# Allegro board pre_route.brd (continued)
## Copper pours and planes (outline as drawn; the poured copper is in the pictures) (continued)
1.5V_PLL on BOTTOM (solid shape): 239.39,45.72 239.39,40.01 238.76,39.37 227.97,39.37 227.33,40.01 227.33,45.72 227.97,46.36 238.76,46.36
1.5V_PLL on L17_PWR3 (solid shape): outline of 3802 points within 0.64,0.64 268.03,236.41
1.5V_PLL_B on TOP (solid shape): 255.91,17.91 255.91,14.61 260.73,9.78 260.73,5.46 257.43,2.16 253.11,2.16 244.47,10.79 234.31,10.79 233.04,12.06 233.04,18.41 234.31,19.69 254.13,19.69
1.5V_PLL_B on BOTTOM (solid shape): 240.03,36.83 240.03,21.59 243.2,18.41 243.2,15.24 242.57,14.61 236.85,14.61 227.33,24.13 227.33,36.83 227.97,37.46 239.39,37.46
1.5V_S_INT on BOTTOM (solid shape): 129.41,291.21 129.41,290.2 128.78,289.56 127,289.56 126.36,288.93 126.36,285.75 127,285.12 129.54,285.12 130.18,284.48 130.18,281.94 129.54,281.31 125.48,281.31 122.3,284.48 117.47,284.48 116.2,285.75 116.2,290.2 117.86,291.85 128.78,291.85
1.5V_S_INT on L5_PWR1 (solid shape): outline of 239 points within 102.55,103.31 170.5,291.78
1.5V_VCCG on L10_IS6 (solid shape): outline of 1022 points within 239.53,215.26 266.7,226.69
1.5V_VCCG on L17_PWR3 (solid shape): 246.19,216.08 246.19,213.69 246.05,213.55 239.44,213.55 238.55,212.66 229.95,212.66 229.81,212.8 229.81,214.95 229.87,214.95 229.94,214.96 230,215 230.44,215.44 230.44,216.2 230.46,216.22 246.05,216.22
1.5V_VCCP on BOTTOM (solid shape): 239.71,225.42 239.2,224.92 237.62,224.92 237.55,224.98 237.55,225.74 238.12,226.31 238.12,227.65 239.71,227.65
1.5V_VCCP on L5_PWR1 (solid shape): 239.99,226.5 240.01,226.48 240.03,226.47 240.06,226.44 240.16,226.34 240.16,225.6 239.47,224.92 238.96,224.92 238.63,224.59 238.63,221.19 238.51,221.04 238.47,220.85 238.6,220.55 238.92,220.43 239.23,220.43 239.45,220.22 239.45,219.89 239.45,219.83 239.45,213.87 239.56,213.55 239.88,213.44 240.16,213.44 240.36,213.23 245.34,213.23 245.44,213.13 245.44,211.85 244.84,211.25 244.82,211.25 229.89,211.25 229.26,211.88 229.26,213.13 229.36,213.23 236.27,213.23 236.35,213.23 238.3,213.23 238.63,213.56 238.63,218.24 238.25,218.62 238.25,218.74 238.26,218.79 238.27,218.85 238.26,218.9 238.25,218.95 238.25,219.82 238.25,219.88 238.25,220.03 238.03,220.26 237.89,220.26 237.24,220.91 237.24,222.96 237.49,223.21 237.49,226.43 237.57,226.5
1.5V_XCVR on TOP (solid shape): 268.61,17.91 268.61,14.61 273.43,9.78 273.43,5.46 270.13,2.16 265.81,2.16 262.51,5.46 262.51,11.05 259.72,13.84 259.72,18.67 260.73,19.69 266.83,19.69
1.5V_XCVR on BOTTOM (solid shape): 245.11,230.76 245.11,230.25 244.22,229.36 244.22,228.73 243.97,228.47 231.65,228.47 231.65,229.87 232.28,230.5 242.32,230.5 242.95,231.14 244.73,231.14
1.5V_XCVR on BOTTOM (solid shape): 264.29,36.07 264.29,32.26 265.68,30.86 267.21,30.86 267.97,30.1 267.97,19.69 273.43,14.22 273.43,5.46 270.13,2.16 265.81,2.16 262.51,5.46 262.51,11.3 259.72,14.1 259.72,36.2 260.35,36.83 263.53,36.83
1.5V_XCVR on L5_PWR1 (solid shape): outline of 1497 points within 195.14,28.26 279.08,249.05
1.5V_XCVR1 on BOTTOM (solid shape): 243.97,226.57 244.54,226 244.54,225.68 244.86,225.36 244.86,224.92 244.09,224.92 243.97,224.79 243.97,224.03 243.71,223.77 242.38,223.77 242.19,223.96 241.74,223.96 241.62,224.09 241.62,224.41 241.74,224.54 242.38,224.54 242.44,224.6 243.33,224.6 243.46,224.73 243.46,225.68 243.33,225.81 242.7,225.81 242.44,226.06 242.44,227.71 243.97,227.71
1.5V_XCVR1 on L5_PWR1 (solid shape): 245.05,225.92 244.95,225.72 244.91,225.5 245.15,224.98 245.71,224.83 245.88,224.83 245.9,224.81 245.9,224.37 245.87,224.35 245.79,224.35 245.74,224.35 245.69,224.35 245.14,223.8 245.69,223.25 245.74,223.25 245.79,223.25 245.9,223.25 245.94,223.21 245.94,222.22 245.8,222.05 245.75,221.84 245.77,221.73 245.81,221.62 245.55,221.37 245.55,219.24 245.45,219.14 245.45,219.13 245.44,219.11 245.44,213.57 245.36,213.49 242.53,213.49 242.44,213.58 242.44,215.57 242.27,215.75 242.27,221.07 242.05,221.28 241.7,221.28 241.68,221.3 241.66,221.31 241.43,221.54 241.43,224.5 241.64,224.5 241.66,224.51 241.73,224.5 241.81,224.49 242.2,224.65 242.36,225.04 242.35,225.16 242.32,225.27 242.32,226.34 242.48,226.5 244.47,226.5
1.5V_XCVR2 on BOTTOM (solid shape): 241.81,226.57 241.3,226.06 241.3,223.77 241.05,223.52 239.52,223.52 238.57,222.57 237.55,222.57 237.49,222.63 237.49,223.2 238.89,224.6 239.39,224.6 240.03,225.23 240.03,227.46 240.22,227.65 241.81,227.65
1.5V_XCVR2 on L5_PWR1 (solid shape): 241.3,225.27 241.27,225.16 241.25,225.04 241.26,224.94 241.29,224.84 241.17,224.72 241.17,221.44 241.45,221.16 241.45,215.64 241.65,215.44 242.02,215.44 242.19,215.28 242.19,213.58 242.1,213.49 240.46,213.49 240.26,213.69 240.26,213.81 240.26,213.87 240.26,219.83 240.15,220.14 239.85,220.27 239.82,220.27 239.78,220.26 239.29,220.75 239.3,220.8 239.31,220.85 239.18,221.15 238.89,221.27 238.89,224.48 239.07,224.66 239.57,224.66 240.41,225.5 240.41,226.32 240.59,226.5 241.3,226.5
1.5V_XCVR3 on BOTTOM (solid shape): 235.33,226.31 235.08,226.06 235.08,225.17 234.76,224.85 232.47,224.85 232.41,224.92 232.41,225.3 232.57,225.46 232.7,225.46 233.81,226.57 233.81,227.65 235.33,227.65
1.5V_XCVR3 on L5_PWR1 (solid shape): 234.7,226.39 234.7,223.45 234.19,222.94 234.19,220.42 234.44,220.17 234.44,219.07 234.44,219.01 234.44,218.85 234.57,218.55 234.88,218.44 235,218.44 235.02,218.44 235.42,218.05 235.43,218.03 235.45,218.01 235.45,217.89 235.56,217.57 235.88,217.45 236.01,217.45 236.44,217.03 236.44,216.98 236.45,216.96 236.45,216.84 236.45,215.88 236.45,215.82 236.45,215.67 236.22,215.44 236.22,213.54 236.17,213.49 234.49,213.49 234.44,213.54 234.44,215.85 234.02,216.27 232.6,216.27 232.26,216.61 232.26,216.81 232.26,216.87 232.26,218.82 232.26,218.85 232.16,219.12 231.9,219.25 231.9,226.5 234.58,226.5
1.5V_XCVR4 on BOTTOM (solid shape): 233.17,226.69 232.09,225.62 232.09,223.52 231.27,222.69 231.27,220.73 231.14,220.6 229.95,220.6 229.62,220.93 229.62,223.01 229.74,223.14 229.74,223.32 230.4,223.98 230.4,225.81 230.15,226.06 229.74,226.06 229.36,226.44 229.36,226.82 229.49,226.95 230.89,226.95 231.58,227.65 233.17,227.65
1.5V_XCVR4 on L5_PWR1 (solid shape): 230.75,226.5 231.65,226.5 231.65,219.2 231.5,219.05 231.44,218.85 231.45,218.79 231.44,218.76 231.44,216.87 231.51,216.62 231.71,216.46 231.79,216.44 231.85,216.43 231.9,216.44 231.96,216.45 232.07,216.45 232.42,216.09 232.44,216.07 232.44,215.68 232.67,215.44 232.82,215.44 232.88,215.44 233.83,215.44 233.89,215.44 234.08,215.44 234.19,215.34 234.19,213.54 234.14,213.49 229.36,213.49 229.26,213.59 229.26,220.64 229.26,220.65 229.26,226.78 229.49,227.01 230.25,227.01
1.5V_XCVR5 on BOTTOM (solid shape): 237.49,226.06 237.24,225.81 237.24,224.35 236.98,224.09 236.6,224.09 236.47,224.22 236.47,224.73 236.35,224.85 235.78,224.85 235.59,225.04 235.59,226.06 235.97,226.44 235.97,227.65 237.49,227.65
1.5V_XCVR5 on L5_PWR1 (solid shape): 237.24,226.44 237.24,223.32 236.98,223.06 236.98,220.8 237.44,220.34 237.44,220.33 237.44,219.88 237.44,219.82 237.44,218.92 237.44,218.89 237.45,218.87 237.45,218.85 237.55,218.58 237.79,218.44 237.79,218.44 237.89,218.44 238.07,218.44 238.38,218.13 238.38,213.67 238.2,213.49 236.55,213.49 236.47,213.57 236.47,215.34 236.58,215.44 236.82,215.44 236.89,215.44 237.01,215.44 237.07,215.5 237.22,215.66 237.26,215.88 237.26,216.84 237.14,217.15 236.82,217.27 236.55,217.27 236.25,217.58 236.25,217.75 236.26,217.8 236.26,217.86 236.14,218.14 235.85,218.26 235.81,218.26 235.78,218.26 235.74,218.26 235.56,218.26 235.25,218.57 235.25,218.58 235.25,218.82 235.18,219.08 234.95,219.24 234.95,220.02 234.44,220.52 234.44,222.83 234.95,223.34 234.95,226.39 235.07,226.5 237.17,226.5
1.25V on TOP (solid shape): 209.17,222.38 209.17,221.23 209.42,220.98 210.44,220.98 210.44,217.68 209.55,217.68 209.55,219.2 209.3,219.46 208.53,219.46 208.41,219.58 208.41,222.38 208.53,222.5 209.04,222.5
1.25V on TOP (solid shape): outline of 227 points within 159.38,244.35 178.44,259.08
1.25V on BOTTOM (solid shape): 178.56,240.16 178.56,235.97 178.31,235.71 175.51,235.71 174.88,236.35 174.88,239.78 175.51,240.41 178.31,240.41
1.25V on BOTTOM (solid shape): 178.56,223.77 178.56,219.58 178.31,219.33 175.51,219.33 174.88,219.96 174.88,223.39 175.51,224.03 178.31,224.03
1.25V on BOTTOM (solid shape): 178.56,213.61 178.56,209.42 178.31,209.17 175.51,209.17 174.88,209.8 174.88,213.23 175.51,213.87 178.31,213.87
1.25V on BOTTOM (solid shape): 178.56,184.28 178.56,180.09 178.31,179.83 175.51,179.83 174.88,180.47 174.88,183.9 175.51,184.53 178.31,184.53
1.25V on BOTTOM (solid shape): 178.56,167.77 178.56,163.58 178.31,163.32 175.51,163.32 174.88,163.96 174.88,167.39 175.51,168.02 178.31,168.02
1.25V on BOTTOM (solid shape): 178.69,250.44 178.69,246.25 178.44,246 175.64,246 175.01,246.63 175.01,250.06 175.64,250.7 178.44,250.7
1.25V on BOTTOM (solid shape): 178.69,156.34 178.69,152.15 178.44,151.89 175.64,151.89 175.01,152.53 175.01,155.96 175.64,156.59 178.44,156.59
1.25V on BOTTOM (solid shape): 178.69,194.56 178.69,191.13 177.55,191.13 177.55,190.37 177.29,190.12 175.64,190.12 175.01,190.75 175.01,194.18 175.64,194.82 178.44,194.82
1.25V on BOTTOM (solid shape): 178.56,142.49 178.56,138.3 178.31,138.05 176.91,138.05 176.66,138.3 176.66,138.81 176.4,139.06 174.88,139.06 174.88,142.11 175.51,142.75 178.31,142.75
1.25V on BOTTOM (solid shape): 178.94,148.21 178.94,144.02 178.69,143.76 177.93,143.76 177.55,144.14 176.66,144.14 176.28,144.53 174.75,144.53 174.75,147.57 176.28,147.57 176.66,147.95 177.29,147.95 177.8,148.46 178.69,148.46
1.25V on BOTTOM (solid shape): 178.31,176.02 178.69,176.02 178.69,172.72 177.55,172.72 177.55,171.83 177.67,171.7 177.67,168.91 177.29,168.53 176.53,168.53 175.77,169.29 174.88,169.29 174.88,176.15 175.89,176.15 176.66,176.91 177.42,176.91
1.25V on L5_PWR1 (solid shape): outline of 1859 points within 164.72,134.24 210.5,261.37
1.25V_GX_SSTL_VREF on TOP (solid shape): 148.59,272.42 148.59,270.38 147.45,269.24 147.45,264.03 147.95,263.53 151.13,263.53 151.89,262.76 151.89,258.57 151.64,258.32 147.32,258.32 146.43,259.21 146.43,272.16 147.07,272.8 148.21,272.8
1.25V_GX_SSTL_VREF on BOTTOM (solid shape): 234.44,202.39 234.44,198.42 234.26,198.25 233.43,198.25 233.25,198.42 233.25,202.39 233.43,202.56 234.26,202.56
1.25V_GX_SSTL_VREF on L4_IS2 (solid shape): outline of 7451 points within 124.46,205.1 235.61,271.4
1.25V_GX_SSTL_VREF on L15_IS9 (solid shape): outline of 392 points within 233.25,200.25 235.43,207.44
2.5V on TOP (solid shape): outline of 295 points within 152.27,251.59 175.26,285.88
2.5V on BOTTOM (solid shape): 160.02,287.66 160.02,280.67 159.38,280.04 154.31,280.04 153.67,280.67 153.67,283.21 152.4,284.48 152.4,287.91 152.78,288.29 159.38,288.29
2.5V_DDR_VDD on L17_PWR3 (solid shape): outline of 141 points within 143.32,132.91 195.77,255.46
2.5V_ENABLE on BOTTOM (solid shape): 156.21,270.26 157.35,269.11 159.45,269.11 159.45,264.16 154.56,264.16 154.05,264.67 152.27,264.67 151.76,265.18 151.76,266.06 155.45,266.06 155.45,268.1 153.42,268.1 153.42,266.06 151.76,266.06 151.76,269.88 153.03,271.15 156.21,271.15
2.5V_GX_IO on BOTTOM (solid shape): 151.76,287.66 151.76,284.1 153.03,282.83 153.03,280.54 152.53,280.04 149.22,280.04 146.69,282.58 146.69,283.97 148.48,283.97 148.48,283.94 148.48,283.88 148.5,283.82 148.52,283.76 148.56,283.7 148.59,283.65 148.64,283.6 148.69,283.57 148.74,283.53 148.8,283.51 148.86,283.49 148.92,283.48 148.99,283.48 149.05,283.48 149.11,283.5 149.17,283.52 149.23,283.55 149.28,283.58 149.33,283.63 149.37,283.68 149.4,283.73 149.43,283.79 149.45,283.85 149.46,283.91 149.47,283.97 149.46,284.04 149.45,284.1 149.43,284.16 149.4,284.22 149.37,284.27 149.33,284.32 149.28,284.36 149.23,284.4 149.17,284.43 149.11,284.45 149.05,284.46 148.99,284.47 148.92,284.47 148.86,284.46 148.8,284.44 148.74,284.41 148.69,284.38 148.64,284.34 148.59,284.29 148.56,284.24 148.52,284.19 148.5,284.13 148.48,284.07 148.48,284 148.48,283.97 146.69,283.97 146.69,287.66 147.32,288.29 151.13,288.29
2.5V_GX_IO on L17_PWR3 (solid shape): outline of 1180 points within 0.64,135.57 238.82,304.16
2.5V_OUT on TOP (solid shape): 156.21,290.83 158.11,290.83 158.11,287.02 146.05,287.02 146.05,290.83 147.95,290.83 150.5,293.37 153.67,293.37
2.5V_OUT on BOTTOM (solid shape): outline of 134 points within 148.59,264.16 174.62,293.37
2.5V_REG_IN on BOTTOM (solid shape): 159.51,274.32 161.35,274.32 161.35,264.16 160.08,264.16 160.08,269.88 157.48,269.88 156.84,270.51 156.84,271.15 156.21,271.78 154.31,271.78 153.54,272.54 153.54,275.34 154.18,275.97 157.86,275.97
3.3V on TOP (solid shape): 51.18,45.21 51.18,41.15 51.05,41.02 48.77,41.02 48.64,41.15 48.64,45.21 48.77,45.34 51.05,45.34
3.3V on TOP (solid shape): 107.31,135.64 107.31,131.06 107.06,130.81 103.76,130.81 103.5,131.06 103.5,135.64 103.76,135.89 107.06,135.89
3.3V on TOP (solid shape): 94.61,252.48 94.61,250.19 94.49,250.06 93.6,250.06 90.17,246.63 90.17,241.3 89.53,240.66 88.9,240.66 88.39,241.17 88.39,252.22 89.03,252.86 94.23,252.86
3.3V on TOP (solid shape): 271.65,202.44 271.65,201.42 271.53,201.29 270.51,201.29 270.13,200.91 270.13,199.77 270,199.64 268.35,199.64 268.22,199.77 268.22,201.42 267.97,201.68 265.94,201.68 265.94,202.69 271.4,202.69
3.3V on TOP (solid shape): 46.74,112.14 46.74,111.38 46.48,111.12 46.48,107.82 46.36,107.7 42.55,107.7 42.42,107.82 42.42,110.74 42.04,111.12 41.78,111.12 41.53,111.38 41.53,112.01 41.78,112.27 46.61,112.27
3.3V on BOTTOM (solid shape): 117.73,19.69 117.73,17.65 117.6,17.53 113.54,17.53 113.41,17.65 113.41,19.69 113.54,19.81 117.6,19.81
3.3V on BOTTOM (solid shape): 124.08,22.99 124.08,20.95 123.95,20.83 119.89,20.83 119.76,20.95 119.76,22.99 119.89,23.11 123.95,23.11
3.3V on BOTTOM (solid shape): 110.11,19.69 110.11,17.65 109.98,17.53 108.46,17.53 108.33,17.65 108.33,18.03 109.09,18.8 109.09,19.81 109.98,19.81
3.3V on L5_PWR1 (solid shape): outline of 190619 points within 0.64,0.64 329.56,304.16
3.3V_CLK1 on TOP (solid shape): 179.96,134.24 179.96,133.48 179.07,132.59 177.42,132.59 176.53,133.48 176.53,135.13 177.04,135.64 178.56,135.64
3.3V_CLK1 on TOP (solid shape): outline of 652 points within 170.18,41.27 205.74,68.58
3.3V_CLK1 on L15_IS9 (solid shape): outline of 1566 points within 170.18,41.27 205.74,68.58
3.3V_CLK2 on TOP (solid shape): outline of 436 points within 172.85,85.6 203.2,108.58
3.3V_CLK2 on L15_IS9 (solid shape): outline of 611 points within 172.72,85.09 189.23,101.35
3.3V_DIV on L5_PWR1 (solid shape): 173.23,224.43 173.23,195.3 171.98,194.06 162.41,194.06 160.78,195.69 160.78,196.14 160.84,196.14 160.85,196.14 161.53,196.6 160.85,197.06 160.84,197.05 160.78,197.05 160.78,202.96 160.84,202.96 161.4,203.45 160.84,203.94 160.78,203.94 160.78,208 157.73,211.05 157.73,215.76 157.83,215.76 157.83,215.72 159.6,215.87 157.83,216.03 157.83,215.99 157.73,215.99 157.73,222.76 157.73,223.65 157.99,223.9 158.03,223.86 158.03,223.85 158.85,223.68 158.68,224.49 158.67,224.49 158.62,224.54 159.51,225.42 172.23,225.42
3.3V_ENABLE on TOP (solid shape): 50.16,273.69 50.16,265.43 49.97,265.24 45.34,265.24 45.34,271.15 44.7,271.78 36.2,271.78 26.67,262.25 26.67,257.18 26.03,256.54 24.13,256.54 23.49,257.18 23.49,265.43 34.29,276.23 47.62,276.23
3.3V_EXT_CLK on L5_PWR1 (solid shape): 145.8,186.58 145.8,169.65 136.7,160.55 132.4,164.85 132.4,187.71 144.67,187.71
3.3V_FAN_OUT on TOP (solid shape): 120.27,277.75 125.35,277.75 125.98,277.11 125.98,273.94 126.62,273.3 129.67,273.3 131.57,271.4 133.86,271.4 134.24,271.02 134.24,269.24 133.86,268.86 131.57,268.86 131.19,268.48 124.46,268.48 123.44,267.46 123.44,263.02 121.28,260.86 118.11,260.86 109.09,251.84 109.09,248.28 108.46,247.65 102.74,247.65 102.23,248.16 102.23,255.27 103,256.03 106.55,256.03 107.95,257.43 107.95,262.25 107.31,262.89 102.74,262.89 102.23,263.4 102.23,270.76 102.74,271.27 106.55,271.27 107.95,272.67 107.95,277.5 107.31,278.13 102.74,278.13 102.23,278.64 102.23,283.21 102.87,283.85 114.17,283.85
3.3V_GX_IO on TOP (solid shape): 94.61,282.96 94.61,280.67 94.49,280.54 93.6,280.54 90.17,277.11 90.17,274.07 89.79,273.69 88.77,273.69 88.39,274.07 88.39,282.7 89.03,283.34 94.23,283.34
3.3V_GX_IO on L11_PWR2 (solid shape): outline of 89532 points within 61.15,0.64 329.56,304.16
3.3V_GX_IO on L15_IS9 (solid shape): outline of 4777 points within 238.25,199.26 250.44,215.44
3.3V_GX_XCVR_AND_CLOCKS on TOP (solid shape): 50.29,259.91 44.89,259.91 44.58,259.59 44.58,256.16 44.83,255.91 44.83,249.56 44.2,248.92 40.77,248.92 40.13,249.56 40.13,255.27 39.5,255.91 34.92,255.91 34.29,256.54 34.29,260.35 34.99,261.05 50.29,261.05
3.3V_LAN on TOP (solid shape): 44.07,122.68 44.45,122.68 44.45,120.27 40.01,120.27 39.75,120.52 39.75,122.68 39.88,122.81 43.94,122.81
3.3V_LAN on L5_PWR1 (solid shape): outline of 356 points within 0.64,115.19 51.82,143.38
3.3V_PLL on L4_IS2 (solid shape): outline of 13184 points within 112.39,129.16 156.21,161.04
3.3V_PS on TOP (solid shape): 150.11,253.62 150.11,249.17 149.86,248.92 146.69,248.92 146.3,248.54 138.43,248.54 138.05,248.92 136.78,248.92 136.4,248.54 135.25,248.54 135,248.79 135,252.98 135.13,253.11 140.21,253.11 141.1,254 141.1,255.4 141.86,256.16 147.57,256.16
3.3V_PS on BOTTOM (solid shape): 149.48,259.97 149.48,254.25 150.75,252.98 150.75,250.44 150.11,249.81 143.13,249.81 142.49,250.44 142.49,259.97 143.13,260.6 148.84,260.6
3.3V_RS232 on L5_PWR1 (solid shape): 28.57,66.32 28.57,56.54 29.84,55.27 29.84,53.06 28.45,51.67 28.45,38.23 23.73,38.23 19.3,42.65 19.3,70.38 20.43,71.5 23.39,71.5
3.3V_S_IO on TOP (solid shape): 94.61,267.72 94.61,265.43 94.49,265.3 93.6,265.3 90.17,261.87 90.17,258.83 89.79,258.44 88.77,258.44 88.39,258.83 88.39,267.46 89.03,268.1 94.23,268.1
3.3V_S_IO on L11_PWR2 (solid shape): outline of 1650 points within 0.64,0.64 168.72,304.16
3.3V_S_IOB on TOP (solid shape): 102.74,261.75 107.06,261.75 107.06,257.43 106.3,256.67 102.49,256.67 101.6,255.78 101.6,254.63 101.09,254.13 93.6,254.13 90.68,257.05 90.68,261.62 93.85,264.8 99.69,264.8
3.3V_S_IOB on BOTTOM (solid shape): 101.47,261.49 101.47,257.05 98.55,254.13 93.34,254.13 90.55,256.92 90.55,261.62 91.19,262.25 91.19,268.1 94.87,268.1
3.3V_SOURCE on TOP (solid shape): 134.75,259.59 134.75,256.54 135,256.29 136.02,256.29 136.27,256.54 136.27,258.57 136.4,258.7 139.95,258.7 140.59,258.06 140.59,254.25 139.95,253.62 133.6,253.62 126.87,254.88 123.09,249.17 123.21,247.95 123.57,246.78 123.57,245.62 122.94,244.98 110.74,244.98 109.98,245.75 109.98,251.46 118.62,260.1 134.24,260.1
3.3V_TEL on TOP (solid shape): 49.91,205.99 49.91,204.47 44.2,198.75 38.61,198.75 38.61,202.56 43.31,202.56 45.47,204.72 45.47,205.36 47.12,207.01 48.9,207.01
3.3V_TEL on BOTTOM (solid shape): 56.13,213.49 56.13,190.63 55.5,189.99 54.23,189.99 53.59,190.63 53.59,202.06 52.96,202.69 38.35,202.69 37.72,203.33 37.72,213.49 38.35,214.12 55.5,214.12
3.3V_XCVR_CLKS on TOP (solid shape): 68.2,252.73 68.2,247.01 67.56,246.38 59.05,246.38 58.55,246.89 58.55,252.86 59.05,253.36 67.56,253.36
3.3V_XCVR_CLKS on L7_IS4 (solid shape): outline of 27347 points within 186.69,46.36 319.41,301.62
3.3V_XCVR_CLKS on L11_PWR2 (solid shape): outline of 68534 points within 43.37,0.64 269.68,254.44
3.3V_XCVR_CLKS_SOURCE on TOP (solid shape): outline of 117 points within 33.66,222 121.28,254.63
3.3V_XPAK on L4_IS2 (solid shape): outline of 530 points within 237.62,111.76 258.95,118.36
3.3VIO_ENABLE on BOTTOM (solid shape): 139.95,279.02 139.95,273.3 139.32,272.67 137.92,272.67 137.41,273.18 137.41,279.02 138.05,279.65 139.32,279.65
3.3VM on TOP (solid shape): 37.46,201.42 37.46,198.75 41.91,194.31 41.91,186.82 38.1,186.82 38.1,191.64 32.13,197.61 32.13,202.56 36.32,202.56
3.3VM on BOTTOM (solid shape): 44.07,201.42 44.07,193.04 43.43,192.41 34.92,192.41 34.35,192.98 34.35,198.75 34.99,199.39 37.46,199.39 38.1,200.03 38.1,201.42 38.73,202.06 43.43,202.06
3.3VM on BOTTOM (solid shape): 266.19,50.04 266.19,43.94 266.06,43.82 264.16,43.82 263.53,44.45 254.63,44.45 253.62,43.43 252.09,43.43 251.84,43.69 251.84,47.37 252.73,48.26 262.38,48.26 264.29,50.16 266.06,50.16
3.3VM on L4_IS2 (solid shape): outline of 37306 points within 0.63,0.63 264.16,289.56
3.3VM_ATX on TOP (solid shape): 35.56,191.13 35.56,186.06 31.75,186.06 31.12,185.42 29.84,185.42 29.21,186.06 29.21,189.23 31.75,191.77 34.92,191.77
3.3VM_ATX on BOTTOM (solid shape): 33.02,251.46 33.02,245.11 31.75,243.84 26.67,243.84 25.4,245.11 25.4,245.75 24.13,247.01 20.95,247.01 19.05,248.92 19.05,251.46 19.69,252.09 32.38,252.09
3.3VM_ATX on L3_IS1 (solid shape): outline of 457 points within 21.59,184.66 38.73,252.09
3.3VM_ATX on L6_IS3 (solid shape): outline of 2861 points within 18.41,185.42 36.2,252.09
5V_CF on L15_IS9 (solid shape): outline of 448 points within 10.16,95.25 21.59,104.14
5V_TEL on TOP (solid shape): 50.16,187.32 50.16,179.07 48.9,177.8 37.46,177.8 36.83,178.44 36.83,183.51 38.1,184.78 41.91,184.78 45.09,187.96 49.53,187.96
5V_TEL on BOTTOM (solid shape): 56.13,188.72 56.13,177.93 55.5,177.29 45.34,177.29 44.7,177.93 44.7,188.72 45.34,189.36 55.5,189.36
5V_XPAK on L4_IS2 (solid shape): outline of 21388 points within 14.61,24.13 262.89,171.45
5VM on TOP (solid shape): 35.56,175.89 34.92,175.26 32.38,175.26 31.75,175.89 31.75,182.88 35.56,182.88
5VM on TOP (solid shape): 44.58,270.38 44.58,264.6 50.29,264.6 50.29,263.33 40.64,263.33 40.13,263.84 40.13,270.64 40.64,271.15 43.82,271.15
5VM on TOP (solid shape): 42.93,236.6 42.93,226.57 42.29,225.93 38.48,225.93 37.85,226.57 37.85,236.6 38.48,237.24 42.29,237.24
5VM on BOTTOM (solid shape): 149.22,203.45 147.83,202.06 147.83,201.42 147.07,200.66 145.41,200.66 145.41,204.98 146.05,205.61 147.07,205.61 147.45,205.99 149.22,205.99
5VM on BOTTOM (solid shape): 283.85,100.33 281.94,98.42 276.23,98.42 273.05,95.25 263.53,95.25 262.25,96.52 262.25,102.87 263.53,104.14 267.34,104.14 272.42,109.22 283.85,109.22
5VM on BOTTOM (solid shape): 62.48,197.61 62.48,179.32 61.59,178.44 61.59,171.45 60.96,170.81 57.79,170.81 56.77,171.83 56.77,197.61 57.4,198.25 61.85,198.25
5VM on BOTTOM (solid shape): 138.81,270 139.45,270 140.21,269.24 140.21,267.59 135.89,267.59 135.25,268.22 135.25,269.24 134.37,270.13 134.37,271.15 134.62,271.4 137.41,271.4
5VM on L7_IS4 (solid shape): outline of 43901 points within 1.27,58.42 161.29,290.83
5VM on L10_IS6 (solid shape): outline of 9479 points within 69.22,41.91 268.61,114.93
5VM_ATX on TOP (solid shape): 36.83,238.12 36.83,226.69 36.2,226.06 27.94,226.06 27.3,226.69 27.3,230.5 27.94,231.14 29.84,231.14 30.48,231.78 30.48,233.68 29.84,234.31 27.94,234.31 27.3,234.95 27.3,238.25 27.94,238.89 36.07,238.89
5VM_ATX on BOTTOM (solid shape): outline of 815 points within 20.32,209.55 31.75,238.76
12V_TEL on TOP (solid shape): 49.53,220.34 49.53,214 48.9,213.36 40.01,213.36 38.73,214.63 38.73,218.44 40.01,219.71 43.18,219.71 44.45,220.98 48.9,220.98
12V_TEL on BOTTOM (solid shape): 55.5,224.28 55.5,216.03 54.86,215.39 43.43,215.39 42.8,216.03 42.8,222.88 43.32,222.88 43.32,222.85 43.33,222.79 43.34,222.73 43.37,222.67 43.4,222.61 43.44,222.56 43.48,222.52 43.53,222.48 43.59,222.45 43.64,222.42 43.7,222.4 43.77,222.39 43.83,222.39 43.89,222.4 43.96,222.41 44.02,222.43 44.07,222.46 44.12,222.5 44.17,222.54 44.21,222.59 44.25,222.64 44.27,222.7 44.29,222.76 44.31,222.82 44.31,222.88 44.31,222.95 44.29,223.01 44.27,223.07 44.25,223.13 44.21,223.18 44.17,223.23 44.12,223.27 44.07,223.31 44.02,223.34 43.96,223.36 43.89,223.37 43.83,223.38 43.77,223.38 43.7,223.37 43.64,223.35 43.59,223.32 43.53,223.29 43.48,223.25 43.44,223.21 43.4,223.16 43.37,223.1 43.34,223.04 43.33,222.98 43.32,222.92 43.32,222.88 42.8,222.88 42.8,224.28 43.43,224.92 54.86,224.92
12VM on TOP (solid shape): 51.82,112.01 51.82,111.38 51.56,111.12 51.56,107.82 51.44,107.7 50.16,107.7 50.04,107.82 50.04,111.12 49.78,111.38 49.78,112.01 49.91,112.14 51.69,112.14
12VM on TOP (solid shape): 37.46,223.52 37.46,214.63 39.37,212.72 41.27,212.72 42.8,211.2 42.8,205.74 42.55,205.49 38.35,205.49 37.72,206.12 37.72,209.93 36.83,210.82 34.29,210.82 31.75,213.36 31.75,224.16 32.38,224.79 36.2,224.79
12VM_ATX on TOP (solid shape): 33.66,210.19 36.2,210.19 36.83,209.55 36.83,205.74 36.2,205.1 27.94,205.1 27.3,205.74 27.3,212.72 27.94,213.36 30.48,213.36
-48V_IN on TOP (solid shape): 121.28,205.74 121.28,200.28 117.6,196.6 110.11,196.6 105.41,201.29 105.41,207.01 106.04,207.64 119.38,207.64
-48V_IN on BOTTOM (solid shape): 123.19,204.72 123.19,201.04 118.74,196.6 112.01,196.6 111.76,196.34 106.43,196.34 105.79,196.98 105.79,204.47 108.97,207.64 120.27,207.64
-48V_PWR on TOP (solid shape): 110.49,213.36 110.49,209.55 109.85,208.91 106.04,208.91 103.5,206.38 103.5,203.2 102.87,202.56 95.25,202.56 94.61,203.2 94.61,214 95.25,214.63 109.22,214.63
-48V_PWR on BOTTOM (solid shape): 111.12,231.14 111.12,209.55 110.49,208.91 108.58,208.91 105.03,205.36 105.03,200.15 104.39,199.52 92.96,199.52 92.33,200.15 92.33,209.04 99.82,216.53 101.73,216.53 101.73,227.08 98.69,230.11 97.68,230.11 97.55,230.12 97.3,230.12 92.96,230.12 92.33,230.76 92.33,236.22 93.6,237.49 104.77,237.49
GND on TOP (solid shape): 88.01,261.62 88.01,258.95 87.5,258.44 86.36,258.44 85.72,259.08 85.72,261.62 86.36,262.25 87.38,262.25
GND on TOP (solid shape): 113.03,301.62 113.03,299.34 112.01,298.32 103.76,298.32 102.87,299.21 102.87,301.62 103.5,302.26 112.39,302.26
GND on TOP (solid shape): 144.4,87.88 144.4,85.6 144.27,85.47 140.21,85.47 140.08,85.6 140.08,87.88 140.21,88.01 144.27,88.01
GND on TOP (solid shape): 150.75,87.88 150.75,85.6 150.62,85.47 146.56,85.47 146.43,85.6 146.43,87.88 146.56,88.01 150.62,88.01
GND on TOP (solid shape): 162.18,87.88 162.18,85.6 162.05,85.47 157.99,85.47 157.86,85.6 157.86,87.88 157.99,88.01 162.05,88.01
GND on TOP (solid shape): 168.53,87.88 168.53,85.6 168.4,85.47 164.34,85.47 164.21,85.6 164.21,87.88 164.34,88.01 168.4,88.01
GND on TOP (solid shape): 88.01,246.38 88.01,241.55 87.5,241.05 84.84,241.05 84.2,241.68 84.2,244.86 86.36,247.01 87.38,247.01
GND on TOP (solid shape): 176.66,259.21 176.66,258.7 176.91,258.44 177.93,258.44 177.93,255.14 177.8,255.02 175.77,255.02 175.64,255.14 175.64,259.21 175.77,259.33 176.53,259.33
GND on TOP (solid shape): 39.37,262.89 38.73,262.25 34.29,262.25 33.02,260.99 33.02,257.81 32.19,256.98 27.56,256.98 27.56,258.7 27.94,259.08 27.94,262.25 36.83,271.15 39.37,271.15
GND on TOP (solid shape): 170.81,264.8 170.81,260.99 170.18,260.35 160.02,260.35 159.38,259.72 154.31,259.72 153.03,260.99 153.03,264.67 153.8,265.43 165.1,265.43 165.73,266.06 169.54,266.06
GND on TOP (solid shape): 69.6,44.58 69.6,44.2 68.96,43.56 68.96,42.42 68.83,42.29 64.52,42.29 64.39,42.42 64.39,43.56 63.75,44.2 63.75,44.58 64.01,44.83 69.34,44.83
GND on TOP (solid shape): 88.52,288.54 88.52,284.73 88.01,284.23 88.01,274.19 87.5,273.69 86.36,273.69 85.72,274.32 85.72,276.86 86.36,277.5 86.36,284.1 85.22,285.24 82.68,285.24 82.17,285.75 82.17,287.91 82.8,288.54 86.87,288.54 87.19,288.86 88.2,288.86
GND on TOP (solid shape): 75.95,44.58 75.95,44.2 75.31,43.56 74.02,43.56 73.89,43.43 73.89,42.39 73.79,42.29 71.75,42.29 71.67,42.38 71.67,43.4 71.5,43.56 70.74,43.56 70.1,44.2 70.1,44.58 70.36,44.83 75.69,44.83
GND on TOP (solid shape): 208.91,200.91 207.14,200.91 207.01,200.79 207.01,197.87 207.14,197.74 208.91,197.74 208.91,197.36 207.14,197.36 207.01,197.23 207.01,194.18 207.14,194.06 209.04,194.06 209.04,193.67 207.14,193.67 207.01,193.55 207.01,190.63 207.26,190.37 209.04,190.37 209.04,189.99 207.14,189.99 206.63,189.48 206.12,189.48 205.99,189.61 205.99,201.04 206.25,201.29 208.91,201.29
GND on TOP (solid shape): 158.62,211.84 158.62,203.58 158.5,203.45 151.82,203.45 151.69,203.58 151.69,206.57 151.69,209.29 151.84,209.29 151.84,206.57 152.96,206.57 152.96,208.09 154.32,208.09 154.32,208 155.89,208 157.61,208 157.61,209.32 155.89,209.32 154.32,209.32 154.32,209.23 152.96,209.23 152.96,209.29 151.69,209.29 151.69,210.49 153.16,211.96 158.5,211.96
GND on TOP (solid shape): 137.41,280.67 137.41,273.99 137.29,273.86 134.3,273.86 131.58,273.86 130.38,273.86 128.91,275.34 128.91,278.07 131.55,278.07 131.55,276.49 131.64,276.49 131.64,275.13 131.58,275.13 131.58,274.02 134.3,274.02 134.3,275.13 132.78,275.13 132.78,276.49 132.87,276.49 132.87,278.07 132.87,279.78 131.55,279.78 131.55,278.07 128.91,278.07 128.91,280.67 129.03,280.8 137.29,280.8
GND on TOP (solid shape): 131.32,267.46 131.32,266.7 131.58,266.44 131.58,266.4 131.62,266.4 132.08,265.94 135.38,265.94 135.89,265.43 135.89,261.62 134.87,260.6 124.21,260.6 123.82,260.99 123.82,264.67 125.41,264.67 125.41,262.13 126.56,262.13 126.56,264.19 127.41,265.05 127.48,265.02 130.3,265.02 131.29,264.03 131.58,264.03 131.58,263.86 134.3,263.86 134.3,264.97 131.54,264.97 131.46,264.94 130.8,265.6 130.8,266.34 129.22,266.34 129.22,265.02 129.1,265.02 129.1,266.34 127.52,266.34 127.52,266.07 127.35,266.07 125.95,264.67 123.82,264.67 123.82,267.21 124.59,267.97 130.81,267.97
GND on TOP (solid shape): 145.8,216.28 145.8,210.06 145.29,209.55 144.53,209.55 144.27,209.29 144.22,209.29 144.22,209.25 143.76,208.79 143.76,205.49 143.26,204.98 139.45,204.98 138.43,205.99 138.43,209.29 141.68,209.29 141.68,206.57 142.8,206.57 142.8,209.33 142.77,209.41 143.43,210.07 144.17,210.07 144.17,211.65 142.85,211.65 142.85,210.57 141.86,209.58 141.86,209.29 138.43,209.29 138.43,214.31 142.02,214.31 142.88,213.45 142.85,213.39 142.85,211.77 144.17,211.77 144.17,213.35 143.89,213.35 143.89,213.52 142.49,214.91 142.49,215.46 139.95,215.46 139.95,214.31 138.43,214.31 138.43,216.66 138.81,217.04 145.03,217.04
GND on TOP (solid shape): outline of 84 points within 27.05,101.22 51.69,105.66
GND on BOTTOM (solid shape): 52.96,201.42 52.96,196.98 52.32,196.34 45.34,196.34 44.7,196.98 44.7,201.42 45.34,202.06 52.32,202.06
GND on BOTTOM (solid shape): 88.52,288.16 88.52,285.75 87.88,285.12 85.09,285.12 84.45,285.75 84.45,288.29 84.96,288.8 87.88,288.8
GND on BOTTOM (solid shape): 71.37,197.61 71.37,190.63 70.74,189.99 63.75,189.99 63.12,190.63 63.12,197.61 63.75,198.25 70.74,198.25
GND on BOTTOM (solid shape): 174.37,214.5 173.1,214.5 172.72,214.12 171.83,214.12 171.7,214.25 171.7,217.3 171.83,217.42 174.37,217.42
GND on BOTTOM (solid shape): 54.86,237.62 54.86,229.36 54.23,228.73 43.05,228.73 42.8,228.98 42.8,237.62 43.43,238.25 54.23,238.25
GND on BOTTOM (solid shape): 87.76,275.21 87.76,272.03 87.12,271.4 85.09,271.4 84.45,272.03 84.45,274.96 85.34,275.84 87.12,275.84
GND on BOTTOM (solid shape): 87.76,259.97 87.76,256.79 87.12,256.16 85.09,256.16 84.45,256.79 84.45,259.72 85.34,260.6 87.12,260.6
GND on BOTTOM (solid shape): 173.1,249.81 174.37,249.81 174.37,246.89 173.1,246.89 172.21,246 171.96,246 171.7,246.25 171.7,250.44 171.83,250.57 172.34,250.57
GND on BOTTOM (solid shape): 173.1,239.65 174.37,239.65 174.37,236.73 173.1,236.73 172.21,235.84 171.96,235.84 171.7,236.09 171.7,240.28 171.83,240.41 172.34,240.41
GND on BOTTOM (solid shape): 173.1,223.14 174.37,223.14 174.37,220.22 173.1,220.22 172.21,219.33 171.96,219.33 171.7,219.58 171.7,223.77 171.83,223.9 172.34,223.9
GND on BOTTOM (solid shape): 173.1,212.98 174.37,212.98 174.37,210.06 173.1,210.06 172.21,209.17 171.96,209.17 171.7,209.42 171.7,213.61 171.83,213.74 172.34,213.74
GND on BOTTOM (solid shape): 173.1,193.93 174.37,193.93 174.37,191.01 173.1,191.01 172.21,190.12 171.96,190.12 171.7,190.37 171.7,194.56 171.83,194.69 172.34,194.69
GND on BOTTOM (solid shape): 173.1,183.77 174.37,183.77 174.37,180.85 173.1,180.85 172.21,179.96 171.96,179.96 171.7,180.21 171.7,184.4 171.83,184.53 172.34,184.53
GND on BOTTOM (solid shape): 173.1,167.26 174.37,167.26 174.37,164.34 173.1,164.34 172.21,163.45 171.96,163.45 171.7,163.7 171.7,167.89 171.83,168.02 172.34,168.02
GND on BOTTOM (solid shape): 87.76,244.73 87.76,239.52 87.12,238.89 85.09,238.89 84.45,239.52 84.45,244.47 85.34,245.36 87.12,245.36
GND on BOTTOM (solid shape): 173.1,176.15 174.37,176.15 174.37,169.42 174.24,169.29 173.1,169.29 172.34,168.53 171.7,168.53 171.58,168.66 171.58,176.78 171.7,176.91 172.34,176.91
GND on BOTTOM (solid shape): 170.31,267.72 170.31,240.79 170.18,240.66 167,240.66 165.48,242.19 155.45,242.19 154.69,242.95 154.69,262.51 155.32,263.14 161.67,263.14 161.92,263.4 161.92,266.7 162.31,267.08 162.69,267.08 163.07,266.7 163.07,263.4 163.32,263.14 168.4,263.14 168.91,263.65 168.91,267.72 169.16,267.97 170.05,267.97
GND on BOTTOM (solid shape): 174.37,156.34 174.37,151.89 174.62,151.64 175.01,151.64 175.13,151.51 175.13,150.75 175.01,150.62 174.62,150.62 174.37,150.37 174.37,149.35 174.62,149.1 175.01,149.1 175.13,148.97 175.13,148.21 175.01,148.08 174.75,148.08 174.37,147.7 174.37,144.14 174.5,144.02 174.88,144.02 175.13,143.76 175.13,143.26 174.88,143 174.5,143 174.24,142.75 174.24,138.81 174.37,138.68 175.01,138.68 175.13,138.56 175.13,138.05 175.01,137.92 173.1,137.92 172.97,138.05 172.97,155.7 172.85,155.83 170.43,155.83 170.31,155.96 170.31,156.46 170.43,156.59 174.12,156.59
GND on L2_GND1 (solid shape): outline of 5497 points within 0.64,0.64 329.56,304.16
GND_HSSI on TOP (solid shape): 309.76,215.78 321.8,215.78 330.26,215.78 330.26,199.53 326.8,199.52 306.78,199.53 287.96,199.53 287.96,204.21 288.96,204.21 288.96,201.53 303.45,201.53 303.45,213.78 288.96,213.78 288.96,211.1 287.96,211.1 287.96,215.78 301.8,215.78
GND_HSSI on TOP (solid shape): 309.76,195.46 321.8,195.46 330.26,195.46 330.26,179.21 326.8,179.2 306.78,179.21 287.96,179.21 287.96,183.89 288.96,183.89 288.96,181.21 303.45,181.21 303.45,193.46 288.96,193.46 288.96,190.78 287.96,190.78 287.96,195.46 301.8,195.46
GND_HSSI on TOP (solid shape): 309.76,175.14 321.8,175.14 330.26,175.14 330.26,158.89 326.8,158.88 306.78,158.89 287.96,158.89 287.96,163.57 288.96,163.57 288.96,160.89 303.45,160.89 303.45,173.14 288.96,173.14 288.96,170.46 287.96,170.46 287.96,175.14 301.8,175.14
GND_HSSI on TOP (solid shape): 309.76,154.82 321.8,154.82 330.26,154.82 330.26,138.57 326.8,138.56 306.78,138.57 287.96,138.57 287.96,143.25 288.96,143.25 288.96,140.57 303.45,140.57 303.45,152.82 288.96,152.82 288.96,150.14 287.96,150.14 287.96,154.82 301.8,154.82
GND_HSSI on TOP (solid shape): 76.58,269.24 76.58,255.27 75.69,254.38 58.8,254.38 57.79,253.36 57.79,247.52 56.58,246.32 50.23,246.32 47.24,249.3 47.24,255.14 47.62,255.52 50.55,255.52 51.31,256.29 51.31,261.37 51.05,261.62 47.75,261.62 47.37,262 47.37,262.38 47.75,262.76 51.05,262.76 51.31,263.02 51.31,269.37 51.82,269.88 75.95,269.88
GND_HSSI on TOP (solid shape): outline of 314 points within 307.09,273.81 330.07,288.8
GND_HSSI on TOP (solid shape): outline of 313 points within 307.09,256.67 330.07,271.65
GND_HSSI on TOP (solid shape): outline of 314 points within 307.09,239.52 330.07,254.51
GND_HSSI on TOP (solid shape): outline of 313 points within 307.09,222.38 330.07,237.36
GND_HSSI on TOP (solid shape): outline of 645 points within 317.47,13.46 332.11,137.16
GND_HSSI on TOP (solid shape): outline of 727 points within 269.88,10.79 308.61,101.6
GND_HSSI on TOP (solid shape): outline of 689 points within 244.6,237.36 293.88,260.73
GND_HSSI on BOTTOM (solid shape): outline of 431 points within 318.72,13.46 332.11,136.49
GND_HSSI on L2_GND1 (solid shape): 232.73,231.06 232.73,225.22 233.47,224.47 244.87,224.47 245.19,224.79 245.73,224.79 246.05,224.47 247.27,224.47 248.16,223.58 248.16,218.82 248.79,218.19 251.21,218.19 251.46,218.44 251.46,224.16 251.78,224.47 256.97,224.47 257.43,224.01 257.43,211.41 256.59,210.57 250.78,210.57 250.51,210.84 250.51,215.15 250.14,215.52 246.71,215.52 246.51,215.72 246.51,216.11 246.08,216.54 231.57,216.54 231.14,216.11 231.14,215.66 231,215.52 229.76,215.52 229.43,215.85 229.43,216.23 229.12,216.54 227.57,216.54 227.2,216.17 227.2,210.77 227,210.57 223.54,210.57 223.39,210.71 223.39,211.79 222.44,212.74 222.44,218.9 221.17,220.17 221.17,223.7 222.44,224.97 222.44,227.15 221.17,228.42 221.17,230.81 221.88,231.52 232.27,231.52
GND_HSSI on L2_GND1 (solid shape): outline of 306 points within 173.36,285.75 204.22,304.16
GND_HSSI on L2_GND1 (solid shape): outline of 636 points within 287.02,138.3 329.56,216.03
GND_HSSI on L4_IS2 (solid shape): outline of 430 points within 317.5,13.45 332.11,136.49
GND_HSSI on L4_IS2 (solid shape): outline of 1488 points within 305.43,220.6 330.28,290.32
GND_HSSI on L4_IS2 (solid shape): outline of 3394 points within 168.4,258.5 239.47,303.68
GND_HSSI on L4_IS2 (solid shape): outline of 5837 points within 228.47,210.44 246.63,227.71
GND_HSSI on L6_IS3 (solid shape): 231.2,227.14 231.2,220.41 231.84,219.77 231.84,219.01 231.9,218.95 231.9,218.76 231.84,218.69 231.84,218.57 231.33,218.06 231.33,217.42 231.2,217.3 230.45,217.3 230.33,217.42 230.33,217.85 230.19,218.19 229.84,218.34 229.5,218.2 229.36,217.86 229.36,217.42 229.23,217.3 228.98,217.3 228.85,217.42 228.85,217.68 228.79,217.74 228.79,217.93 228.85,218 228.85,218.69 228.79,218.76 228.79,218.95 228.85,219.01 228.85,219.27 228.93,219.34 229.83,219.34 229.84,219.34 230.2,219.49 230.35,219.85 230.35,219.87 230.46,220.9 230.45,220.94 230.3,221.29 229.95,221.44 229.93,221.44 229.29,221.44 229.17,221.55 229.17,226.24 229.24,226.24 229.26,226.22 230.11,226.57 229.26,226.91 229.24,226.9 229.17,226.9 229.17,227.52 229.36,227.71 230.63,227.71
GND_HSSI on L6_IS3 (solid shape): outline of 1181 points within 233.36,211.58 239.71,227.71
GND_HSSI on L6_IS3 (solid shape): outline of 1288 points within 239.77,211.58 246.76,227.71
GND_HSSI on L6_IS3 (solid shape): outline of 3359 points within 168.02,258.5 239.47,303.68
GND_HSSI on L9_IS5 (solid shape): outline of 732 points within 239.71,215.26 266.7,226.69
GND_HSSI on L10_IS6 (solid shape): outline of 1346 points within 223.44,237.36 313.06,290.98
GND_HSSI on L10_IS6 (solid shape): outline of 1640 points within 269.88,10.79 308.61,129.54
GND_HSSI on L14_GND3 (solid shape): outline of 6940 points within 0.64,0.64 329.56,304.16
GND_HSSI on L16_IS10 (solid shape): outline of 737 points within 172.72,85.09 189.48,101.6
GND_HSSI on L16_IS10 (solid shape): outline of 1309 points within 170.18,41.27 205.74,68.58
GND_HSSI on L16_IS10 (solid shape): outline of 1319 points within 229.29,214.25 250.39,216.08
GND_HSSI on L17_PWR3 (solid shape): outline of 2038 points within 172.66,0.64 329.56,304.16
GND_PLL on L8_GND2 (solid shape): outline of 7299 points within 0.64,0.64 329.56,304.16
GND_PLL on L17_PWR3 (solid shape): 221.66,205.04 223.09,205.04 223.58,205.53 223.58,206.04 223.73,206.18 225.09,206.18 225.23,206.04 225.23,203.15 224.22,202.14 224.22,201.75 223.95,201.49 223.6,201.49 223.46,201.63 223.46,202.26 223.09,202.63 220.8,202.63 219.53,203.9 212.65,203.9 211.5,202.76 209.22,202.76 206.95,200.48 206.95,195.4 204.15,192.61 204.15,179.5 206.95,176.71 206.95,150.7 205.68,149.43 205.68,137.84 206.31,137.21 206.31,133.17 204.65,131.51 196.88,131.51 196.56,131.19 195.83,131.19 195.77,131.25 195.77,132.64 196.15,133.02 196.15,135.19 197.18,135.19 199.6,137.6 201.25,137.6 202.76,139.11 202.76,149.65 203.64,150.54 203.64,176.23 200.85,179.02 200.85,184.96 201.49,185.6 201.49,194.23 203.26,196.01 203.26,202.49 207.03,206.25 207.26,206.25 207.39,206.12 207.39,204.85 207.77,204.47 209.42,204.47 210.44,205.49 210.44,206.76 210.88,207.2 219.5,207.2
GND_RTN on BOTTOM (solid shape): 91.06,236.6 91.06,230 100.33,220.73 100.33,218.95 91.06,209.68 91.06,198.37 96.39,193.04 99.69,193.04 101.73,195.07 111.63,195.07 112.08,194.63 118.68,194.63 119,194.31 120.02,194.31 123.19,191.13 123.19,188.59 118.62,184.02 104.65,184.02 102.87,182.25 91.19,182.25 83.44,189.99 83.44,236.22 84.71,237.49 90.17,237.49
VCCA on BOTTOM (solid shape): 23.49,139.7 23.49,135.89 22.23,134.62 18.92,134.62 18.03,135.51 18.03,139.45 18.54,139.95 23.24,139.95
VCCQP on TOP (solid shape): 144.65,265.43 145.8,265.43 146.05,265.18 146.05,263.65 145.8,263.4 144.4,263.4 143.38,264.41 143.38,264.8 143.13,265.05 140.84,265.05 140.72,265.18 140.72,266.19 140.84,266.32 143.76,266.32
VCCQP on BOTTOM (solid shape): 144.65,265.56 147.19,265.56 148.59,264.16 148.59,263.14 148.34,262.89 146.3,262.89 145.8,262.38 141.35,262.38 141.22,262.51 141.22,263.14 143.27,263.14 143.27,263.11 143.28,263.05 143.29,262.99 143.32,262.93 143.35,262.87 143.39,262.82 143.43,262.78 143.48,262.74 143.53,262.7 143.59,262.68 143.65,262.66 143.72,262.65 143.78,262.65 143.84,262.65 143.91,262.67 143.96,262.69 144.02,262.72 144.07,262.76 144.12,262.8 144.16,262.85 144.2,262.9 144.22,262.96 144.24,263.02 144.26,263.08 144.26,263.14 144.26,263.21 144.24,263.27 144.22,263.33 144.2,263.39 144.16,263.44 144.12,263.49 144.07,263.53 144.02,263.57 143.96,263.6 143.91,263.62 143.84,263.63 143.78,263.64 143.72,263.64 143.65,263.63 143.59,263.61 143.53,263.58 143.48,263.55 143.43,263.51 143.39,263.47 143.35,263.41 143.32,263.36 143.29,263.3 143.28,263.24 143.27,263.18 143.27,263.14 141.22,263.14 141.22,265.68 141.48,265.94 144.27,265.94
APS on BOTTOM (solid shape): 306.07,123.82 306.07,110.49 303.53,107.95 286.39,107.95 284.61,109.73 271.65,109.73 270.76,108.84 258.7,108.84 257.43,110.11 257.43,112.14 258.19,112.9 277.5,112.9 277.88,112.52 291.97,112.52 292.99,111.51 297.81,111.51 298.45,112.14 298.45,118.11 299.21,118.87 302.01,118.87 302.39,119.25 302.39,124.08 302.77,124.46 305.44,124.46
APS_INPUT on BOTTOM (solid shape): 259.59,138.56 259.59,137.41 258.19,136.02 257.05,136.02 256.92,136.14 256.92,138.56 257.05,138.68 259.46,138.68
APS_INPUT on BOTTOM (solid shape): outline of 84 points within 277.5,113.03 292.8,129.29
BST on BOTTOM (solid shape): 289.81,123.32 289.81,121.92 289.56,121.67 286.58,121.67 286,122.24 286,122.87 286.13,123 288.48,123 288.93,123.44 289.69,123.44
NET_2_I2_1 on TOP (solid shape): 85.72,268.48 85.72,263.53 85.09,262.89 81.66,262.89 81.03,263.53 81.03,268.61 81.79,269.37 84.84,269.37
NET_2_I2_1 on BOTTOM (solid shape): 85.72,267.46 85.72,261.75 83.95,259.97 83.95,257.68 83.57,257.3 81.41,257.3 81.03,257.68 81.03,268.1 85.09,268.1
NET_2_I17_1 on TOP (solid shape): 85.72,283.72 85.72,278.77 85.09,278.13 81.66,278.13 81.03,278.77 81.03,283.85 81.79,284.61 84.84,284.61
NET_2_I17_1 on BOTTOM (solid shape): 85.72,282.7 85.72,276.99 83.95,275.21 83.95,272.92 83.57,272.54 81.41,272.54 81.03,272.92 81.03,283.34 85.09,283.34
NET_2_I21_2 on BOTTOM (solid shape): 135,268.48 135,267.34 135.38,266.95 139.83,266.95 140.21,266.57 140.21,264.03 138.05,261.87 138.05,258.06 136.78,256.79 132.33,256.79 131.44,257.68 131.44,265.94 131.83,266.32 133.86,266.32 134.04,266.5 134.04,268.48 134.16,268.61 134.87,268.61
NET_2_I22_2 on BOTTOM (solid shape): 133.99,272.29 133.99,269.88 133.6,269.49 131.06,269.49 129.41,271.15 129.41,272.92 130.18,273.69 132.59,273.69
NET_2_I31_2 on BOTTOM (solid shape): 52.96,194.44 52.96,190.63 52.32,189.99 45.34,189.99 44.7,190.63 44.7,194.44 45.34,195.07 52.32,195.07
NET_2_I41_1 on TOP (solid shape): 85.72,253.24 85.72,248.28 85.09,247.65 81.66,247.65 81.03,248.28 81.03,253.36 81.79,254.13 84.84,254.13
NET_2_I41_1 on BOTTOM (solid shape): 85.72,252.22 85.72,246.51 83.95,244.73 83.95,242.19 83.69,241.94 81.28,241.94 81.03,242.19 81.03,252.86 85.09,252.86
NET_2_I149_IN on TOP (solid shape): 102.74,276.99 107.06,276.99 107.06,272.67 106.3,271.91 102.36,271.91 101.47,271.02 101.47,269.88 100.96,269.37 93.6,269.37 90.68,272.29 90.68,276.86 93.85,280.04 99.69,280.04
NET_2_I149_IN on BOTTOM (solid shape): 101.47,276.73 101.47,272.29 98.55,269.37 92.33,269.37 90.68,271.02 90.68,276.61 91.19,277.11 91.19,283.34 94.87,283.34
NET_2_I150_IN on TOP (solid shape): 101.6,248.92 101.6,247.65 102.74,246.51 107.06,246.51 107.06,242.19 103.76,238.89 93.6,238.89 90.68,241.81 90.68,246.38 93.85,249.56 100.96,249.56
NET_2_I150_IN on BOTTOM (solid shape): 101.47,246.25 101.47,241.81 98.55,238.89 93.34,238.89 90.55,241.68 90.55,246.38 91.19,247.01 91.19,252.86 94.87,252.86
NET_3_I10_2 on TOP (solid shape): 151.13,299.72 151.13,295.91 147.32,292.1 146.05,292.1 144.78,290.83 144.78,285.75 144.14,285.12 141.6,285.12 140.34,283.85 135.25,283.85 134.62,284.48 134.62,287.02 139.06,291.47 139.06,299.09 140.97,300.99 149.86,300.99
NET_3_I10_2 on BOTTOM (solid shape): 141.6,288.29 141.6,285.12 140.34,283.85 135.25,283.85 134.62,284.48 134.62,287.02 136.53,288.93 140.97,288.93
NET_3_I14_ADJ on BOTTOM (solid shape): 168.34,269.05 168.34,264.35 168.15,264.16 165.23,264.16 165.16,264.22 165.16,269.05 165.35,269.24 168.15,269.24
NET_3_I15_2 on BOTTOM (solid shape): 138.56,209.42 143.76,209.42 144.14,209.04 144.14,207.01 144.32,206.83 146.3,206.83 146.43,206.71 146.43,205.99 146.3,205.87 145.16,205.87 144.78,205.49 144.78,201.04 144.4,200.66 141.86,200.66 139.7,202.82 135.89,202.82 134.62,204.09 134.62,209.04 135.13,209.55 138.43,209.55
NET_3_I16_1 on TOP (solid shape): 165.1,299.09 165.1,292.1 168.28,288.93 168.28,284.48 167.51,283.72 165.86,283.72 163.19,286.39 160.66,286.39 159.38,287.66 159.38,290.83 158.11,292.1 156.84,292.1 153.03,295.91 153.03,299.72 154.31,300.99 163.19,300.99
NET_3_I16_1 on BOTTOM (solid shape): 167.64,286.39 167.64,284.23 167.26,283.85 163.96,283.85 162.94,284.86 162.94,288.29 165.73,288.29
NET_3_I17_IN on TOP (solid shape): 137.79,299.72 137.79,292.1 135,289.31 128.02,289.31 127,288.29 121.28,288.29 120.65,288.93 120.65,299.72 121.28,300.36 127,300.36 128.27,301.62 135.89,301.62
NET_3_I22_1 on TOP (solid shape): 95.25,299.72 95.25,288.93 94.61,288.29 89.53,288.29 88.58,289.24 80.96,289.24 78.1,292.1 78.1,297.81 80.64,300.36 94.61,300.36
NET_3_I22_2 on TOP (solid shape): 107.31,296.55 107.31,289.56 106.68,288.93 102.23,288.93 102.23,294.64 102.87,295.28 102.87,296.55 103.5,297.18 106.68,297.18
NET_3_I22_2 on BOTTOM (solid shape): 106.68,292.74 106.68,289.56 105.41,288.29 102.23,288.29 101.6,288.93 101.6,292.74 102.23,293.37 106.04,293.37
NET_3_I33_VCCQP on TOP (solid shape): 144.14,200.03 144.14,197.1 143.26,196.22 143.26,195.33 143.51,195.07 143.51,192.02 142.88,191.39 142.24,191.39 141.6,192.02 141.6,193.29 141.1,193.8 141.1,196.34 141.99,197.23 142.49,197.23 142.88,197.61 142.88,200.03 143,200.15 144.02,200.15
NET_3_I33_VCCQP on BOTTOM (solid shape): 143.51,197.74 144.14,197.1 143.38,196.34 143.38,194.44 142.88,193.93 141.6,193.93 141.1,194.44 141.1,196.34 141.6,196.85 141.6,199.26 141.99,199.64 143.51,199.64
NET_3_I34_1 on TOP (solid shape): 130.94,205.74 130.94,198.88 131.57,198.25 132.84,198.25 133.99,197.1 133.99,193.29 131.44,190.75 127,190.75 126.36,191.39 126.36,202.56 126.62,202.82 126.62,204.09 126.36,204.34 126.36,205.99 127,206.63 130.05,206.63
NET_3_I34_1 on BOTTOM (solid shape): 138.43,197.74 138.43,192.02 137.79,191.39 132.08,191.39 130.81,190.12 128.27,190.12 127.63,190.75 127.63,197.74 128.27,198.37 137.79,198.37
NET_3_I37_2 on TOP (solid shape): 113.03,295.91 113.03,294.64 113.66,294 113.66,288.93 109.22,288.93 108.58,289.56 108.58,296.55 109.22,297.18 111.76,297.18
NET_3_I37_2 on BOTTOM (solid shape): 114.3,292.74 114.3,288.93 113.66,288.29 110.49,288.29 109.22,289.56 109.22,292.74 109.85,293.37 113.66,293.37
NET_3_I56_1 on TOP (solid shape): 136.65,229.74 136.65,207.26 136.02,206.63 134.62,206.63 133.99,205.99 133.99,204.72 134.24,204.47 136.53,204.47 136.53,200.91 135.89,200.28 132.08,200.28 131.44,200.91 131.44,205.99 125.09,212.34 125.09,216.53 124.46,217.17 124.46,227.97 124.47,227.97 124.47,229.88 125.09,230.5 135.89,230.5
NET_3_I121_2 on BOTTOM (solid shape): 151.51,210.69 151.51,208.28 149.86,206.63 147.95,206.63 147.32,207.26 147.32,209.8 148.59,211.07 151.13,211.07
NET_4_I17_1 on TOP (solid shape): 150.75,272.54 150.75,270 151.64,269.11 151.64,264.67 147.83,264.67 147.83,268.99 148.97,270.13 148.97,272.67 149.22,272.92 150.37,272.92
NET_4_I18_1 on TOP (solid shape): 158.75,257.81 158.75,248.92 158.11,248.28 151.76,248.28 151.13,248.92 151.13,254 149.86,255.27 149.86,257.18 150.5,257.81 151.76,257.81 152.4,258.44 158.11,258.44
NET_4_I18_1 on TOP (solid shape): 161.16,278.38 161.16,274.07 158.11,274.07 157.61,274.57 157.61,277.37 157.23,277.75 157.23,277.88 159.91,277.88 159.91,277.84 159.91,277.78 159.93,277.72 159.95,277.66 159.99,277.61 160.02,277.55 160.07,277.51 160.12,277.47 160.17,277.44 160.23,277.41 160.29,277.39 160.35,277.38 160.42,277.38 160.48,277.39 160.54,277.4 160.6,277.42 160.66,277.45 160.71,277.49 160.76,277.53 160.8,277.58 160.83,277.63 160.86,277.69 160.88,277.75 160.89,277.81 160.9,277.88 160.89,277.94 160.88,278 160.86,278.06 160.83,278.12 160.8,278.17 160.76,278.22 160.71,278.26 160.66,278.3 160.6,278.33 160.54,278.35 160.48,278.37 160.42,278.37 160.35,278.37 160.29,278.36 160.23,278.34 160.17,278.32 160.12,278.28 160.07,278.24 160.02,278.2 159.99,278.15 159.95,278.09 159.93,278.03 159.91,277.97 159.91,277.91 159.91,277.88 157.23,277.88 157.23,278.51 157.35,278.64 160.91,278.64
NET_4_I18_1 on L6_IS3 (solid shape): outline of 739 points within 145.41,250.19 161.92,278.77
NET_4_I48_1 on TOP (solid shape): 169.93,245.24 169.93,244.47 169.67,244.22 169.16,244.22 168.28,243.33 168.28,241.3 167.64,240.66 151.13,240.66 143.89,233.43 138.43,233.43 134.62,237.24 134.62,242.57 137.79,245.75 153.03,245.75 154.31,247.01 168.15,247.01
NET_14_I103_D1A on BOTTOM (solid shape): 291.53,124.97 291.78,124.71 292.74,124.71 293.62,123.82 296.86,123.82 297.88,122.81 297.88,112.33 297.56,112.01 293.5,112.01 293.12,112.39 293.12,118.24 293.37,118.49 293.37,122.17 292.74,122.81 290.58,122.81 290.26,123.13 290.26,123.76 289.94,124.08 288.93,124.08 288.93,125.73 290.45,127.25 291.53,127.25
XCVR_RX_N0C on TOP (solid shape): 330.28,51.76 328.51,51.76 326.74,51.91 326.74,52.26 328.51,52.4 330.28,52.4
XCVR_RX_N0C on TOP (solid shape): 324.88,52.26 324.88,51.9 324,51.72 323.31,51.72 323.22,51.82 323.22,52.32 323.32,52.43 324,52.43
XCVR_RX_N1C on TOP (solid shape): 330.28,97.51 328.5,97.51 326.73,97.65 326.73,98 328.5,98.15 330.28,98.15
XCVR_RX_N1C on TOP (solid shape): 324.85,98.01 324.85,97.65 323.97,97.47 323.27,97.47 323.17,97.57 323.17,98.08 323.27,98.18 323.97,98.18
XCVR_RX_N2C on TOP (solid shape): 275.83,246.9 275.92,246.77 275.95,246.62 275.95,244.26 276.42,242.76 276.43,242.67 276.44,242.63 276.44,242.56 275.94,242.56 275.94,242.27 275.22,242.27 275.22,242.57 274.74,242.57 274.74,242.67 274.76,242.77 274.86,243.14 274.99,243.5 275.23,244.25 275.23,244.26 275.23,246.48 274.6,247.12 274.6,247.14 275.08,247.62 275.11,247.62
